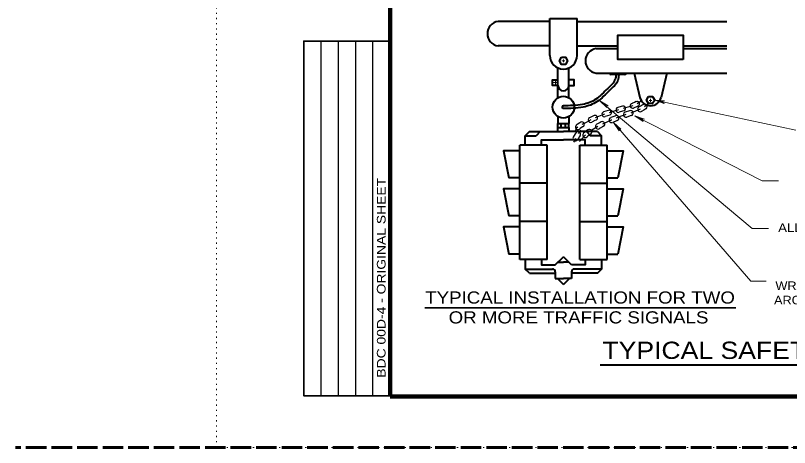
# Model space of a CAD drawing. Extents: x 312583 to 312854, y 144419 to 144597.
# Drawn here: x 312583.5 to 312651.6, y 144418.6 to 144456.6 of the extents above; entities that cross this region are included whole.
import ezdxf
from ezdxf.enums import TextEntityAlignment as Align

# ---------------------------------------------------------------- set-up
doc = ezdxf.new("R2010")
doc.units = 0
doc.header["$LTSCALE"] = 0.3
doc.linetypes.add('DOTTED', pattern=[1.5, 0.3, -1.2])
doc.linetypes.add('LONG_DASHED', pattern=[7.5, 6, -1.5])
for name, color, linetype, lineweight in [('1', 7, 'Continuous', 40), ('62', 7, 'DOTTED', 13), ('63', 7, 'LONG_DASHED', 60)]:
    doc.layers.add(name, color=color, linetype=linetype, lineweight=lineweight)

msp = doc.modelspace()

# ---------------------------------------------------------------- linework, layer by layer
at = {"layer": '1'}
for p, q in [((312630.5284, 144456.096), (312625.9821, 144456.096)), ((312630.5284, 144453.106), (312630.5284, 144456.3413)), ((312630.5284, 144456.3413), (312632.9281, 144456.3413)), ((312632.9281, 144453.106), (312632.9281, 144456.3413)), ((312632.9281, 144456.096), (312646.1071, 144456.096)), ((312630.5284, 144453.9416), (312625.9821, 144453.9416)), ((312632.9281, 144453.9416), (312636.5238, 144453.9416)), ((312634.6071, 144453.704), (312636.5238, 144453.704)), ((312642.2738, 144453.9416), (312646.1071, 144453.9416)), ((312642.2738, 144453.704), (312646.1071, 144453.704)), ((312631.2491, 144449.38), (312631.2491, 144452.0096)), ((312632.2074, 144449.38), (312632.2074, 144452.0096)), ((312634.6071, 144451.5496), (312646.1071, 144451.5496)), ((312637.1218, 144451.427), (312635.9181, 144451.427)), ((312637.9574, 144451.5496), (312638.4634, 144449.4106)), ((312640.8324, 144451.5496), (312640.3264, 144449.4106)), ((312631.2491, 144447.724), (312631.2491, 144447.1183)), ((312632.2074, 144447.724), (312632.2074, 144447.1183)), ((312631.2491, 144446.758), (312631.2491, 144447.1183)), ((312631.2491, 144447.1183), (312632.2074, 144447.1183)), ((312631.5404, 144446.758), (312631.5404, 144447.1183)), ((312631.9161, 144446.758), (312631.9161, 144447.1183)), ((312632.2074, 144446.758), (312632.2074, 144447.1183)), ((312628.7344, 144446.3976), (312631.7321, 144446.3976)), ((312629.6928, 144446.3976), (312629.3324, 144446.0373)), ((312631.2491, 144446.3976), (312631.2491, 144446.758)), ((312631.2491, 144446.758), (312632.2074, 144446.758)), ((312634.7221, 144446.3976), (312631.7321, 144446.3976)), ((312632.2074, 144446.758), (312632.2074, 144446.3976)), ((312633.7638, 144446.3976), (312634.1241, 144446.0373)), ((312628.3741, 144445.2016), (312628.3741, 144446.0373)), ((312635.0824, 144445.2016), (312635.0824, 144446.0373)), ((312630.2908, 144445.2016), (312627.8988, 144445.2016)), ((312627.8988, 144441.8436), (312627.8988, 144445.2016)), ((312630.2908, 144441.8436), (312630.2908, 144445.2016)), ((312633.1658, 144445.2016), (312635.5654, 144445.2016)), ((312633.1658, 144441.8436), (312633.1658, 144445.2016)), ((312635.5654, 144441.8436), (312635.5654, 144445.2016)), ((312627.8988, 144442.3266), (312626.9404, 144442.3266)), ((312635.5654, 144442.3266), (312636.5238, 144442.3266)), ((312630.2908, 144441.8436), (312627.8988, 144441.8436)), ((312627.8988, 144438.4933), (312627.8988, 144441.8436)), ((312630.2908, 144438.4933), (312630.2908, 144441.8436)), ((312633.1658, 144441.8436), (312635.5654, 144441.8436)), ((312633.1658, 144438.4933), (312633.1658, 144441.8436)), ((312635.5654, 144438.4933), (312635.5654, 144441.8436)), ((312627.8988, 144438.9686), (312626.9404, 144438.9686)), ((312635.5654, 144438.9686), (312636.5238, 144438.9686)), ((312627.8988, 144435.1353), (312627.8988, 144438.4933)), ((312635.5654, 144435.1353), (312635.5654, 144438.4933)), ((312627.8988, 144435.6183), (312626.9404, 144435.6183)), ((312631.0114, 144434.66), (312631.7321, 144435.373)), ((312632.4451, 144434.66), (312631.7321, 144435.373)), ((312635.5654, 144435.6183), (312636.5238, 144435.6183)), ((312630.2908, 144435.1353), (312627.8988, 144435.1353)), ((312628.3741, 144435.1353), (312628.3741, 144434.2996)), ((312631.2491, 144434.8976), (312631.7321, 144434.8976)), ((312632.2074, 144434.8976), (312631.7321, 144434.8976)), ((312633.1658, 144435.1353), (312635.5654, 144435.1353)), ((312635.0824, 144435.1353), (312635.0824, 144434.2996)), ((312628.7344, 144433.9393), (312631.0114, 144433.9393)), ((312631.0114, 144434.0543), (312631.0114, 144433.4563)), ((312632.4451, 144434.0543), (312632.4451, 144433.4563)), ((312634.7221, 144433.9393), (312632.4451, 144433.9393)), ((312631.0114, 144433.4563), (312631.7321, 144433.4563)), ((312631.2031, 144433.4563), (312631.7321, 144432.935)), ((312632.4451, 144433.4563), (312631.7321, 144433.4563)), ((312632.2534, 144433.4563), (312631.7321, 144432.935)), ((312634.9649, 144425.8578), (312681.5977, 144425.8578))]:
    msp.add_line(p, q, dxfattribs=at)
at = {"layer": '1', "lineweight": 25}
for p, q in [((312610.4087, 144423.1446), (312610.4087, 144454.3629)), ((312611.9315, 144423.1446), (312611.9315, 144454.3629)), ((312613.4543, 144423.1446), (312613.4543, 144454.3629)), ((312614.9772, 144423.1446), (312614.9772, 144454.3629)), ((312635.6804, 144448.2606), (312635.2664, 144448.1303)), ((312635.8108, 144447.8466), (312635.3968, 144447.7163)), ((312633.2578, 144446.5126), (312633.0201, 144446.2213)), ((312632.8208, 144445.7996), (312632.6214, 144445.4776))]:
    msp.add_line(p, q, dxfattribs=at)
at = {"layer": '1', "lineweight": 13}
for p, q in [((312631.7321, 144452.623), (312631.6018, 144452.623)), ((312631.7321, 144452.623), (312631.7321, 144452.7533)), ((312631.7321, 144452.623), (312631.8548, 144452.623)), ((312631.7321, 144452.623), (312631.7321, 144452.5003)), ((312631.0268, 144450.7293), (312631.0268, 144450.9516)), ((312631.0268, 144450.7293), (312630.7738, 144450.7293)), ((312631.0268, 144450.7293), (312631.2491, 144450.7293)), ((312631.0268, 144450.7293), (312631.0268, 144450.4686)), ((312648.3228, 144437.88), (312634.9291, 144449.1193)), ((312634.9291, 144449.1193), (312635.5424, 144448.506)), ((312634.9291, 144449.1193), (312635.6804, 144448.6746)), ((312639.3988, 144449.15), (312639.2684, 144449.15)), ((312639.3988, 144449.15), (312639.3988, 144449.2803)), ((312639.3988, 144449.15), (312639.5214, 144449.15)), ((312639.3988, 144449.15), (312639.3988, 144449.0196)), ((312652.1791, 144446.5356), (312639.7591, 144449.1653)), ((312639.7591, 144449.1653), (312640.6254, 144449.0963)), ((312639.7591, 144449.1653), (312640.5794, 144448.8816)), ((312640.6254, 144449.0963), (312640.3341, 144449.0426)), ((312640.5794, 144448.8816), (312640.3341, 144449.0426)), ((312635.5424, 144448.506), (312635.3891, 144448.759)), ((312635.6804, 144448.6746), (312635.3891, 144448.759)), ((312638.0264, 144447.7853), (312638.7548, 144447.2946)), ((312638.0264, 144447.7853), (312638.8544, 144447.4786)), ((312638.7548, 144447.2946), (312638.5554, 144447.5093)), ((312638.8544, 144447.4786), (312638.5554, 144447.5093)), ((312636.1328, 144447.1873), (312636.6311, 144446.4666)), ((312636.1328, 144447.1873), (312636.7921, 144446.6046)), ((312636.6311, 144446.4666), (312636.5238, 144446.7426)), ((312636.7921, 144446.6046), (312636.5238, 144446.7426)), ((312649.7641, 144437.88), (312648.3228, 144437.88))]:
    msp.add_line(p, q, dxfattribs=at)
at = {"layer": '1', "lineweight": 35}
msp.add_line((312619.5397, 144430.8952), (312646.8957, 144430.8952), dxfattribs=at)
at = {"layer": '1', "lineweight": 158}
msp.add_line((312616.5, 144423.0846), (312849, 144423.0846), dxfattribs=at)
msp.add_lwpolyline([(312616.5, 144423.1446), (312616.5, 144585.0846), (312849, 144585.0846)], dxfattribs=at)
at = {"layer": '1', "lineweight": 35}
msp.add_lwpolyline([(312616.5, 144423.1446), (312608.8858, 144423.1446), (312608.8858, 144454.3629), (312616.5, 144454.3629)], dxfattribs=at)
at = {"layer": '1'}
for points in [[(312642.2738, 144452.7456), (312636.5238, 144452.7456), (312636.5238, 144454.9), (312642.2738, 144454.9)], [(312631.5481, 144452.9373), (312631.9084, 144452.9373), (312632.0848, 144452.623), (312631.9084, 144452.3163), (312631.5481, 144452.3163), (312631.3718, 144452.623)], [(312639.2148, 144449.4796), (312639.5751, 144449.4796), (312639.7591, 144449.1653), (312639.5751, 144448.8586), (312639.2148, 144448.8586), (312639.0384, 144449.1653)]]:
    msp.add_lwpolyline(points, close=True, dxfattribs=at)
for points in [[(312631.2491, 144450.4686), (312630.7738, 144450.4686), (312630.7738, 144450.9516), (312631.2491, 144450.9516)], [(312632.2074, 144450.4686), (312632.6904, 144450.4686), (312632.6904, 144450.9516), (312632.2074, 144450.9516)], [(312628.7344, 144446.3976), (312628.3741, 144446.0373), (312629.3324, 144446.0373)], [(312634.7221, 144446.3976), (312635.0824, 144446.0373), (312634.1241, 144446.0373)], [(312629.8154, 144445.2016), (312629.8154, 144445.677), (312631.7321, 144445.677)], [(312633.6488, 144445.2016), (312633.6488, 144445.677), (312631.7321, 144445.677)], [(312627.8988, 144444.7186), (312626.4574, 144444.7186), (312626.9404, 144442.3266)], [(312635.5654, 144444.7186), (312636.9991, 144444.7186), (312636.5238, 144442.3266)], [(312627.8988, 144441.3683), (312626.4574, 144441.3683), (312626.9404, 144438.9686)], [(312635.5654, 144441.3683), (312636.9991, 144441.3683), (312636.5238, 144438.9686)], [(312627.8988, 144438.0103), (312626.4574, 144438.0103), (312626.9404, 144435.6183)], [(312630.2908, 144435.1353), (312630.2908, 144438.4933), (312627.8988, 144438.4933)], [(312633.1658, 144435.1353), (312633.1658, 144438.4933), (312635.5654, 144438.4933)], [(312635.5654, 144438.0103), (312636.9991, 144438.0103), (312636.5238, 144435.6183)], [(312629.8154, 144435.1353), (312629.8154, 144434.66), (312631.0114, 144434.66)], [(312633.6488, 144435.1353), (312633.6488, 144434.66), (312632.4451, 144434.66)], [(312628.7344, 144433.9393), (312628.3741, 144434.2996), (312630.7738, 144434.2996)], [(312634.7221, 144433.9393), (312635.0824, 144434.2996), (312632.6904, 144434.2996)]]:
    msp.add_lwpolyline(points, dxfattribs=at)
at = {"layer": '1', "lineweight": 25}
for points in [[(312638.1184, 144449.035), (312637.9804, 144448.9583), (312637.8194, 144448.897), (312637.7658, 144448.874)], [(312638.5784, 144449.0886), (312638.2488, 144448.8586), (312638.2258, 144448.8433)], [(312636.5774, 144448.3066), (312635.9871, 144448.1303), (312635.7494, 144448.0536)], [(312636.9301, 144448.644), (312636.8151, 144448.6056), (312636.5161, 144448.5136)], [(312637.0528, 144448.2223), (312636.9378, 144448.1916), (312636.6388, 144448.0996)], [(312637.8271, 144448.667), (312637.3901, 144448.5443), (312636.9914, 144448.4293)], [(312637.5741, 144448.2376), (312637.5511, 144448.23), (312637.1601, 144448.1073)], [(312638.4788, 144448.3603), (312638.0648, 144448.184), (312637.6508, 144448.0306)], [(312638.3254, 144448.6516), (312638.1721, 144448.5673), (312637.9651, 144448.483), (312637.8884, 144448.46)], [(312638.7394, 144448.7743), (312638.5784, 144448.6593), (312638.4021, 144448.5673), (312638.3944, 144448.5673)], [(312638.9848, 144448.3986), (312638.8008, 144448.276), (312638.5938, 144448.1686), (312638.5631, 144448.1533)], [(312639.2148, 144448.8586), (312638.8698, 144448.5903), (312638.8621, 144448.5826)], [(312634.4384, 144447.8083), (312634.3081, 144447.7546), (312634.0321, 144447.6166)], [(312635.3354, 144447.9233), (312635.1054, 144447.8543), (312634.5228, 144447.609)], [(312636.3014, 144447.793), (312636.2401, 144447.7623), (312635.8951, 144447.6243)], [(312637.2291, 144447.8926), (312637.1754, 144447.8696), (312636.7231, 144447.7163), (312636.3858, 144447.586)], [(312637.7274, 144447.8236), (312637.6968, 144447.8083), (312637.2981, 144447.678)], [(312633.2578, 144447.218), (312633.1734, 144447.172), (312632.9511, 144447.0263), (312632.8591, 144446.9496)], [(312633.4648, 144446.8346), (312633.3958, 144446.804), (312633.2118, 144446.6813), (312633.1428, 144446.62)], [(312634.1318, 144447.425), (312633.7178, 144447.2103), (312633.3574, 144447.0263)], [(312634.7681, 144446.8423), (312634.3694, 144446.6123), (312634.0091, 144446.367)], [(312634.6071, 144447.4096), (312634.4921, 144447.3636), (312634.2314, 144447.2256)], [(312635.0594, 144447.264), (312634.9521, 144447.2103), (312634.7374, 144447.0876), (312634.6531, 144447.0416)], [(312635.2588, 144446.8653), (312635.1668, 144446.8116), (312634.9598, 144446.7043), (312634.8754, 144446.6506)], [(312635.9794, 144447.4173), (312635.9258, 144447.3943), (312635.5961, 144447.2563), (312635.2741, 144447.1183), (312635.1591, 144447.0646)], [(312636.4701, 144447.379), (312636.4088, 144447.3483), (312636.0638, 144447.2103)], [(312632.8438, 144446.3133), (312632.7594, 144446.1983), (312632.5831, 144445.8993)], [(312633.0048, 144446.781), (312632.8898, 144446.689), (312632.8438, 144446.6353), (312632.7901, 144446.5356), (312632.7518, 144446.436)], [(312633.8864, 144446.5586), (312633.7638, 144446.4743), (312633.4954, 144446.2596)], [(312634.1394, 144446.183), (312634.0321, 144446.114), (312633.8098, 144445.9223)], [(312633.2118, 144446.0526), (312633.1351, 144445.953), (312632.9894, 144445.6923)], [(312633.6641, 144446.091), (312633.6104, 144446.045), (312633.1351, 144445.539)]]:
    msp.add_lwpolyline(points, dxfattribs=at)
at = {"layer": '1', "lineweight": 13}
for points in [[(312650.6458, 144442.0736), (312649.2121, 144442.0736), (312638.0264, 144447.7853)], [(312649.5571, 144433.2263), (312648.2078, 144433.2263), (312636.1328, 144447.1873)]]:
    msp.add_lwpolyline(points, dxfattribs=at)
at = {"layer": '1'}
msp.add_circle((312631.7283, 144448.552), 0.9583, dxfattribs=at)
for centre, radius, start, end in [((312626.1307, 144455.0207), 1.0888, 98.04578, 261.95423), ((312634.7557, 144452.6249), 1.0888, 98.04578, 261.95423), ((312631.7283, 144453.1041), 1.1979, 180, 0), ((312635.921, 144451.5468), 0.1198, 180, 270), ((312637.1189, 144451.5468), 0.1198, 270, 0), ((312631.7283, 144450.4686), 0.4792, 180, 0), ((312639.3949, 144449.6299), 0.9581, 193.28615, 346.71385), ((312631.7283, 144448.552), 0.1198, 90, 259.29865), ((312630.7699, 144434.0572), 0.2396, 0, 90), ((312632.6866, 144434.0572), 0.2396, 90, 180)]:
    msp.add_arc(centre, radius, start, end, dxfattribs=at)
at = {"layer": '1', "lineweight": 25}
for centre, radius, start, end in [((312637.826, 144448.669), 0.217, 106.04447, 286.04447), ((312638.224, 144448.8396), 0.217, 305.01684, 125.01684), ((312635.7462, 144448.0545), 0.217, 287.61348, 107.61348), ((312636.5755, 144448.3088), 0.217, 106.80876, 286.80876), ((312636.9916, 144448.432), 0.217, 285.64546, 105.64546), ((312637.6492, 144448.0292), 0.2232, 290.30305, 110.30305), ((312638.4779, 144448.3598), 0.2232, 113.16566, 293.16566), ((312638.8647, 144448.5815), 0.2232, 307.75072, 127.75072), ((312634.133, 144447.4229), 0.217, 116.69353, 296.69353), ((312634.5246, 144447.6091), 0.217, 292.62989, 112.62989), ((312635.3326, 144447.9232), 0.217, 107.61348, 287.61348), ((312635.974, 144447.4151), 0.2232, 112.58365, 292.58365), ((312636.3872, 144447.5838), 0.2232, 291.75162, 111.75162), ((312637.2249, 144447.891), 0.2232, 109.02974, 289.02974), ((312633.0026, 144446.7851), 0.217, 130.95638, 310.95638), ((312633.3608, 144447.0276), 0.217, 297.59492, 117.59492), ((312634.7651, 144446.8438), 0.2232, 120.48689, 300.48689), ((312635.1556, 144447.0598), 0.2232, 296.63126, 116.63126), ((312633.0273, 144446.1816), 0.2232, 323.93366, 143.93366), ((312633.6564, 144446.0964), 0.2232, 136.88276, 316.88276), ((312634.0099, 144446.3691), 0.2232, 303.93366, 123.93366), ((312632.7884, 144445.8045), 0.2232, 156.88276, 336.88276)]:
    msp.add_arc(centre, radius, start, end, dxfattribs=at)
at = {"layer": '1'}
for points in [[(312636.5928, 144451.381), (312636.5084, 144450.898), (312635.8108, 144450.0393), (312634.6991, 144449.035), (312633.4724, 144448.552), (312631.7091, 144448.4293)], [(312636.3551, 144451.4116), (312636.2861, 144450.9976), (312635.6344, 144450.2003), (312634.5764, 144449.242), (312633.4188, 144448.7896), (312631.7321, 144448.6746)]]:
    msp.add_spline(points, degree=3, dxfattribs=at)
at = {"layer": '62'}
msp.add_line((312601.2, 144418.5846), (312601.2, 144596.7846), dxfattribs=at)
msp.add_lwpolyline([(312601.2, 144418.5846), (312853.5, 144418.5846), (312853.5, 144596.7846)], dxfattribs=at)
at = {"layer": '63'}
msp.add_line((312851.75, 144418.5846), (312583.526, 144418.5846), dxfattribs=at)

# ---------------------------------------------------------------- texts
at = {"layer": '1', "width": 1.2}
msp.add_text('BDC 00D-4 - ORIGINAL SHEET', height=0.7614, rotation=90, dxfattribs=at).set_placement((312616.0832, 144424.7374))
at = {"layer": '1'}
for s, width, p in [('ALLOW 610 MM SLACK', 1.15, (312650.6206, 144437.5532)), ('WRAP CHAIN ONE TURN', 1.1, (312650.3836, 144432.451)), ('AROUND SPIDER ASSEMBLY', 1.1, (312650.2602, 144431.186))]:
    msp.add_text(s, height=0.76, dxfattribs=dict(at, width=width)).set_placement(p)
at = {"layer": '1', "width": 1.15}
for s, height, p in [('TYPICAL INSTALLATION FOR TWO', 1.07, (312633.1942, 144431.2558)), ('OR MORE TRAFFIC SIGNALS', 1.07, (312633.0599, 144429.5077)), ('TYPICAL SAFETY CHAIN INSTALLATIONS', 1.52, (312658.2801, 144426.3847))]:
    msp.add_text(s, height=height, dxfattribs=at).set_placement(p, align=Align.CENTER)

doc.saveas('drawing.dxf')
